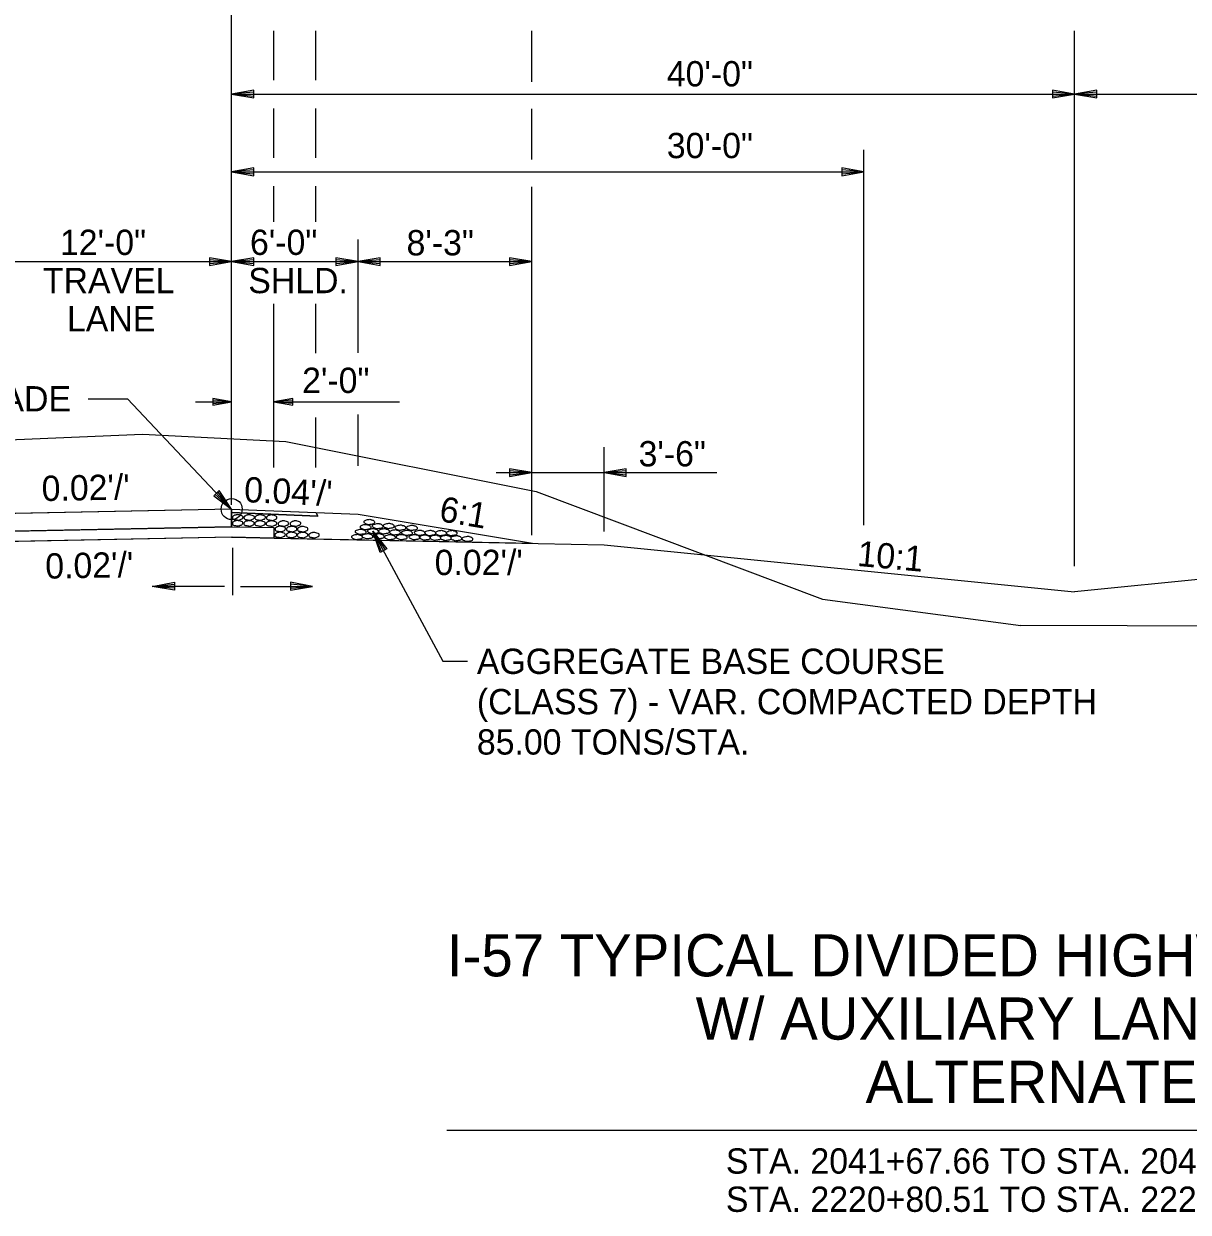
# Model space of a CAD drawing. Extents: x 1734743 to 1735935, y 759845 to 763831.
# Drawn here: x 1735698.4 to 1735753.6, y 760376.2 to 760432.6 of the extents above; entities that cross this region are included whole.
import ezdxf

# ---------------------------------------------------------------- set-up
doc = ezdxf.new("R2010")
doc.units = 0
for name, color, linetype in [('1', 7, 'Continuous'), ('19', 7, 'Continuous'), ('8', 7, 'Continuous'), ('Level 1', 7, 'Continuous'), ('R_Prop Surface', 7, 'Continuous')]:
    doc.layers.add(name, color=color, linetype=linetype)

# ---------------------------------------------------------------- blocks, each defined once
blk = doc.blocks.new('TM')
at = {"layer": '8'}
for p, q in [((-120.309, 21.181), (-119.787, -20.829)), ((0, 0), (-120.309, 21.181)), ((-31.382, 2.945), (-120.176, 10.512)), ((-119.787, -20.829), (0, 0)), ((-119.911, -10.826), (-31.307, -3.057))]:
    blk.add_line(p, q, dxfattribs=at)
blk = doc.blocks.new('ROCKS')
at = {"layer": '1'}
blk.add_spline([(0.013, 0.06), (0.053, 0.053), (0.107, 0.033), (0.133, 0.013), (0.133, -0.007), (0.12, -0.033), (0.107, -0.04), (0.073, -0.053), (0.033, -0.067), (0.013, -0.067), (-0.02, -0.06), (-0.06, -0.053), (-0.087, -0.047), (-0.113, -0.02), (-0.113, -0.007), (-0.107, 0.02), (-0.087, 0.033), (-0.067, 0.047), (-0.033, 0.053), (-0.02, 0.06), (0.013, 0.06)], degree=3, dxfattribs=at)

msp = doc.modelspace()

# ---------------------------------------------------------------- linework, layer by layer
at = {"layer": '19'}
for p, q in [((1735708.232, 760425.539), (1735708.232, 760434.612)), ((1735708.232, 760425.535), (1735708.232, 760433.567)), ((1735710.232, 760429.881), (1735710.232, 760432.22)), ((1735712.229, 760429.881), (1735712.229, 760432.22)), ((1735722.472, 760429.805), (1735722.472, 760432.214)), ((1735748.233, 760406.824), (1735748.233, 760432.22)), ((1735709.282, 760429.405), (1735708.232, 760429.221)), ((1735708.232, 760429.221), (1735709.282, 760429.038)), ((1735708.232, 760429.221), (1735748.232, 760429.221)), ((1735709.282, 760429.309), (1735708.512, 760429.248)), ((1735708.512, 760429.195), (1735709.282, 760429.125)), ((1735709.282, 760429.038), (1735709.282, 760429.405)), ((1735747.182, 760429.405), (1735747.182, 760429.038)), ((1735748.232, 760429.221), (1735747.182, 760429.405)), ((1735747.952, 760429.248), (1735747.182, 760429.309)), ((1735747.182, 760429.038), (1735748.232, 760429.221)), ((1735747.182, 760429.125), (1735747.952, 760429.195)), ((1735749.282, 760429.405), (1735748.232, 760429.221)), ((1735748.232, 760429.221), (1735749.282, 760429.038)), ((1735748.232, 760429.221), (1735788.232, 760429.221)), ((1735749.282, 760429.309), (1735748.512, 760429.248)), ((1735748.512, 760429.195), (1735749.282, 760429.125)), ((1735749.282, 760429.038), (1735749.282, 760429.405)), ((1735710.232, 760426.194), (1735710.232, 760428.533)), ((1735712.229, 760426.194), (1735712.229, 760428.533)), ((1735722.472, 760426.118), (1735722.472, 760428.527)), ((1735738.232, 760408.779), (1735738.232, 760426.581)), ((1735709.282, 760425.718), (1735708.232, 760425.535)), ((1735708.232, 760410.562), (1735708.232, 760425.535)), ((1735708.232, 760425.535), (1735709.282, 760425.351)), ((1735708.232, 760425.535), (1735738.232, 760425.535)), ((1735709.282, 760425.622), (1735708.512, 760425.561)), ((1735708.512, 760425.509), (1735709.282, 760425.438)), ((1735709.282, 760425.351), (1735709.282, 760425.718)), ((1735737.182, 760425.719), (1735737.182, 760425.351)), ((1735738.232, 760425.535), (1735737.182, 760425.719)), ((1735737.952, 760425.561), (1735737.182, 760425.622)), ((1735737.182, 760425.351), (1735738.232, 760425.535)), ((1735737.182, 760425.439), (1735737.952, 760425.509)), ((1735710.232, 760423.159), (1735710.232, 760424.847)), ((1735712.229, 760423.159), (1735712.229, 760424.847)), ((1735722.472, 760408.305), (1735722.472, 760424.823)), ((1735714.232, 760416.957), (1735714.232, 760422.325)), ((1735696.232, 760421.275), (1735708.232, 760421.275)), ((1735707.182, 760421.459), (1735707.182, 760421.092)), ((1735708.232, 760421.275), (1735707.182, 760421.459)), ((1735707.952, 760421.302), (1735707.182, 760421.363)), ((1735707.182, 760421.092), (1735708.232, 760421.275)), ((1735707.182, 760421.179), (1735707.952, 760421.249)), ((1735709.282, 760421.459), (1735708.232, 760421.275)), ((1735708.232, 760421.275), (1735714.232, 760421.275)), ((1735708.232, 760421.275), (1735709.282, 760421.091)), ((1735709.282, 760421.363), (1735708.512, 760421.302)), ((1735708.512, 760421.249), (1735709.282, 760421.179)), ((1735709.282, 760421.091), (1735709.282, 760421.459)), ((1735713.182, 760421.459), (1735713.182, 760421.092)), ((1735714.232, 760421.275), (1735713.182, 760421.459)), ((1735713.952, 760421.302), (1735713.182, 760421.363)), ((1735713.182, 760421.092), (1735714.232, 760421.275)), ((1735713.182, 760421.179), (1735713.952, 760421.249)), ((1735715.282, 760421.459), (1735714.232, 760421.275)), ((1735714.232, 760421.275), (1735722.472, 760421.275)), ((1735714.232, 760421.275), (1735715.282, 760421.091)), ((1735715.282, 760421.363), (1735714.512, 760421.302)), ((1735714.512, 760421.249), (1735715.282, 760421.179)), ((1735715.282, 760421.091), (1735715.282, 760421.459)), ((1735721.422, 760421.459), (1735721.422, 760421.092)), ((1735722.472, 760421.275), (1735721.422, 760421.459)), ((1735722.192, 760421.302), (1735721.422, 760421.363)), ((1735721.422, 760421.092), (1735722.472, 760421.275)), ((1735721.422, 760421.179), (1735722.192, 760421.249)), ((1735710.232, 760411.515), (1735710.232, 760419.279)), ((1735712.229, 760416.937), (1735712.229, 760419.279)), ((1735708.232, 760409.737), (1735708.232, 760417.551)), ((1735706.51, 760414.629), (1735708.232, 760414.629)), ((1735707.338, 760414.785), (1735707.338, 760414.472)), ((1735708.232, 760414.629), (1735707.338, 760414.785)), ((1735707.994, 760414.651), (1735707.338, 760414.703)), ((1735707.338, 760414.472), (1735708.232, 760414.629)), ((1735707.338, 760414.547), (1735707.994, 760414.606)), ((1735711.127, 760414.787), (1735710.232, 760414.63)), ((1735710.232, 760414.63), (1735711.127, 760414.473)), ((1735710.232, 760414.63), (1735716.198, 760414.63)), ((1735711.127, 760414.712), (1735710.471, 760414.652)), ((1735710.471, 760414.608), (1735711.127, 760414.555)), ((1735711.127, 760414.473), (1735711.127, 760414.787)), ((1735714.232, 760411.588), (1735714.232, 760414.028)), ((1735712.229, 760411.515), (1735712.229, 760413.875)), ((1735725.901, 760408.483), (1735725.901, 760412.473)), ((1735720.79, 760411.266), (1735731.251, 760411.266)), ((1735721.422, 760411.45), (1735721.422, 760411.082)), ((1735722.472, 760411.266), (1735721.422, 760411.45)), ((1735722.192, 760411.292), (1735721.422, 760411.354)), ((1735721.422, 760411.082), (1735722.472, 760411.266)), ((1735721.422, 760411.17), (1735722.192, 760411.24)), ((1735726.951, 760411.45), (1735725.901, 760411.266)), ((1735725.901, 760411.266), (1735726.951, 760411.082)), ((1735726.951, 760411.354), (1735726.181, 760411.292)), ((1735726.181, 760411.24), (1735726.951, 760411.17)), ((1735726.951, 760411.082), (1735726.951, 760411.45)), ((1735707.644, 760410.426), (1735707.381, 760410.173)), ((1735707.381, 760410.173), (1735708.232, 760409.537)), ((1735707.444, 760410.232), (1735708.02, 760409.72)), ((1735708.057, 760409.754), (1735707.58, 760410.358)), ((1735708.232, 760409.537), (1735707.644, 760410.426)), ((1735708.232, 760409.537), (1735682.232, 760409.017)), ((1735708.232, 760409.537), (1735714.232, 760409.297)), ((1735708.232, 760409.537), (1735708.232, 760408.703)), ((1735708.232, 760409.37), (1735712.314, 760409.207)), ((1735714.232, 760409.297), (1735722.503, 760407.919)), ((1735708.232, 760408.703), (1735682.232, 760408.183)), ((1735708.232, 760408.703), (1735710.232, 760408.663)), ((1735710.232, 760408.663), (1735710.232, 760408.163)), ((1735714.938, 760408.488), (1735718.251, 760402.319)), ((1735715.273, 760407.479), (1735714.938, 760408.488)), ((1735714.938, 760408.488), (1735715.596, 760407.649)), ((1735708.25, 760408.204), (1735680.251, 760407.644)), ((1735708.232, 760408.203), (1735682.232, 760407.683)), ((1735708.232, 760408.203), (1735722.508, 760407.918)), ((1735708.25, 760408.204), (1735710.25, 760408.164)), ((1735710.25, 760408.164), (1735725.913, 760407.85)), ((1735715.348, 760407.52), (1735715.045, 760408.229)), ((1735715.088, 760408.252), (1735715.511, 760407.609)), ((1735725.913, 760407.85), (1735748.233, 760405.618)), ((1735725.913, 760407.85), (1735748.233, 760405.618)), ((1735770.549, 760407.85), (1735748.233, 760405.618)), ((1735770.549, 760407.85), (1735748.233, 760405.618)), ((1735708.269, 760407.706), (1735708.269, 760405.453)), ((1735715.596, 760407.649), (1735715.273, 760407.479)), ((1735707.89, 760405.869), (1735704.469, 760405.869)), ((1735708.648, 760405.869), (1735712.069, 760405.869)), ((1735718.251, 760402.319), (1735719.422, 760402.319)), ((1735718.448, 760380.087), (1735778.085, 760380.087))]:
    msp.add_line(p, q, dxfattribs=at)
for points in [[(1735701.415, 760414.77), (1735703.288, 760414.77), (1735708.232, 760409.537)], [(1735613.569, 760412.168), (1735650.334, 760412.409), (1735661.883, 760412.749), (1735665.836, 760412.246), (1735671.317, 760412.306), (1735681.258, 760412.702), (1735687.89, 760412.661), (1735696.883, 760412.784), (1735704.001, 760413.089)], [(1735704.001, 760413.089), (1735710.795, 760412.749), (1735722.683, 760410.368), (1735736.27, 760405.268), (1735745.673, 760404.013)], [(1735712.314, 760409.207), (1735708.232, 760409.37), (1735708.232, 760409.37), (1735708.232, 760409.537), (1735708.232, 760409.537), (1735708.232, 760409.537), (1735712.229, 760409.377), (1735712.229, 760409.377), (1735712.229, 760409.377), (1735712.314, 760409.207), (1735712.314, 760409.207), (1735712.314, 760409.207)], [(1735680.233, 760407.643), (1735680.233, 760408.143), (1735708.232, 760408.703), (1735710.232, 760408.663), (1735710.232, 760408.163), (1735710.232, 760408.163), (1735710.232, 760408.163), (1735708.232, 760408.203), (1735680.233, 760407.643)], [(1735780.028, 760401.943), (1735755.777, 760403.99), (1735745.673, 760404.013)]]:
    msp.add_lwpolyline(points, dxfattribs=at)
msp.add_lwpolyline([(1735708.232, 760409.537), (1735682.232, 760409.017), (1735682.232, 760408.183), (1735708.232, 760408.703)], close=True, dxfattribs=at)
msp.add_circle((1735708.232, 760409.537), 0.5, dxfattribs=at)
at = {"layer": 'R_Prop Surface'}
msp.add_line((1735712.229, 760409.377), (1735712.314, 760409.207), dxfattribs=at)

# ---------------------------------------------------------------- block references
at = {"layer": '19', "xscale": 0.008761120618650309}
for p, yscale, rotation in [((1735704.466, 760405.865), -0.008761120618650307, -179.20057588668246), ((1735712.07, 760405.865), 0.008761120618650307, -0.7994241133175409)]:
    msp.add_blockref('TM', p, dxfattribs=dict(at, yscale=yscale, rotation=rotation))
at = {"layer": 'Level 1', "xscale": 2.011654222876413}
for p, yscale, rotation in [((1735708.493, 760408.871), 2.011654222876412, 1.33680650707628), ((1735708.501, 760409.151), 2.011654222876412, 1.33680650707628), ((1735709.037, 760408.867), 2.011654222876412, 1.33680650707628), ((1735709.044, 760409.147), 2.011654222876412, 1.33680650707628), ((1735709.558, 760408.862), 2.011654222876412, 1.33680650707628), ((1735709.566, 760409.142), 2.011654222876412, 1.33680650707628), ((1735710.101, 760408.858), 2.011654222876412, 1.33680650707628), ((1735710.109, 760409.138), 2.011654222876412, 1.33680650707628), ((1735710.669, 760408.858), 2.011654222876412, 1.33680650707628), ((1735711.24, 760408.858), 2.011654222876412, 1.33680650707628), ((1735714.782, 760408.929), -2.011654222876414, 178.00441377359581), ((1735715.183, 760408.735), -2.011654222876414, 178.00441377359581), ((1735715.706, 760408.743), -2.011654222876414, 178.00441377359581), ((1735710.51, 760408.322), 2.011654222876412, 1.33680650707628), ((1735710.518, 760408.602), 2.011654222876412, 1.33680650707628), ((1735711.054, 760408.318), 2.011654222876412, 1.33680650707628), ((1735711.061, 760408.598), 2.011654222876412, 1.33680650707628), ((1735711.575, 760408.313), 2.011654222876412, 1.33680650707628), ((1735711.583, 760408.593), 2.011654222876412, 1.33680650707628), ((1735712.118, 760408.309), 2.011654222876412, 1.33680650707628), ((1735714.199, 760408.219), -2.011654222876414, 178.00441377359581), ((1735714.376, 760408.464), -2.011654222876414, 178.00441377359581), ((1735714.608, 760408.69), -2.011654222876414, 178.00441377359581), ((1735714.695, 760408.255), -2.011654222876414, 178.00441377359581), ((1735714.959, 760408.493), -2.011654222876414, 178.00441377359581), ((1735715.227, 760408.253), -2.011654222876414, 178.00441377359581), ((1735715.486, 760408.489), -2.011654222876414, 178.00441377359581), ((1735715.761, 760408.212), -2.011654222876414, 178.00441377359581), ((1735716, 760408.44), -2.011654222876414, 178.00441377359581), ((1735716.259, 760408.663), -2.011654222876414, 178.00441377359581), ((1735716.321, 760408.215), -2.011654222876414, 178.00441377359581), ((1735716.573, 760408.419), -2.011654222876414, 178.00441377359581), ((1735716.806, 760408.654), -2.011654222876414, 178.00441377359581), ((1735716.929, 760408.213), -2.011654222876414, 178.00441377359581), ((1735717.181, 760408.417), -2.011654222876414, 178.00441377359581), ((1735717.419, 760408.195), -2.011654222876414, 178.00441377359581), ((1735717.674, 760408.41), -2.011654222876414, 178.00441377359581), ((1735717.916, 760408.187), -2.011654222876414, 178.00441377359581), ((1735718.184, 760408.408), -2.011654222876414, 178.00441377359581), ((1735718.412, 760408.174), -2.011654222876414, 178.00441377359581), ((1735718.696, 760408.407), -2.011654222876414, 178.00441377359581), ((1735718.911, 760408.159), -2.011654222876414, 178.00441377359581), ((1735719.44, 760408.128), -2.011654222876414, 178.00441377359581)]:
    msp.add_blockref('ROCKS', p, dxfattribs=dict(at, yscale=yscale, rotation=rotation))

# ---------------------------------------------------------------- texts
at = {"layer": '19'}
for s, height, p in [('40\'-0"', 1.2, (1735728.881, 760429.586)), ('30\'-0"', 1.2, (1735728.881, 760426.182)), ('12\'-0"', 1.2, (1735700.084, 760421.59)), ('6\'-0"', 1.2, (1735709.102, 760421.592)), ('8\'-3"', 1.2, (1735716.532, 760421.572)), ('TRAVEL', 1.2, (1735699.276, 760419.778)), ('SHLD.', 1.2, (1735709.021, 760419.779)), ('LANE', 1.2, (1735700.419, 760417.965)), ('2\'-0"', 1.2, (1735711.576, 760415.045)), ('PROFILE GRADE', 1.2, (1735687.591, 760414.17)), ('3\'-6"', 1.2, (1735727.541, 760411.563)), ("0.02'/'", 1.2, (1735717.866, 760406.409)), ('I-57 TYPICAL DIVIDED HIGHWAY SECTION', 2, (1735718.448, 760387.375)), ('W/ AUXILIARY LANE RT.', 2, (1735730.251, 760384.375)), ('ALTERNATE 2', 2, (1735738.314, 760381.375)), ('STA. 2041+67.66 TO STA. 2047+98.67', 1.2, (1735731.684, 760378.019)), ('STA. 2220+80.51 TO STA. 2222+91.87', 1.2, (1735731.684, 760376.206))]:
    msp.add_text(s, height=height, dxfattribs=at).set_placement(p)
for s, rotation, p in [("0.02'/'", 1.0931, (1735699.227, 760409.916)), ("0.04'/'", 357.3887, (1735708.805, 760409.87)), ('6:1', 350.5489, (1735718.035, 760408.974)), ('10:1', 354.8422, (1735737.886, 760406.846)), ("0.02'/'", 1.0121, (1735699.397, 760406.237)), ('AGGREGATE BASE COURSE', 360, (1735719.869, 760401.719)), ('(CLASS 7) - VAR. COMPACTED DEPTH', 360, (1735719.869, 760399.807)), ('85.00 TONS/STA.', 360, (1735719.869, 760397.895))]:
    msp.add_text(s, height=1.2, rotation=rotation, dxfattribs=at).set_placement(p)

doc.saveas('drawing.dxf')
